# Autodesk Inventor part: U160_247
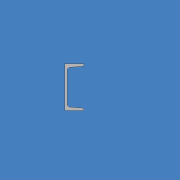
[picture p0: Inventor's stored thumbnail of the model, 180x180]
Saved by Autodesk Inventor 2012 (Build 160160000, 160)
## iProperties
Company: CAD-Verlag
Shininess: 64.0
Length Units: 11269
Angle Units: 11279
Time Units: 11290
Mass Units: 11283
Length Display Precision: 3
Angle Display Precision: 2
Compacted: True
Part Number: U160_247
Document SubType Name: Modeling
Created: 2004-09
Material: Standard
Designer: Greiling
Manufacturer: Standard
Standards Organization: Custom
Density: 1 g/cm^3
Density: 0.0
Volumn: 0.0
Area: 0.0
PropertySet Name: Model Information
Control State: 0
Master: False
Checked Out: False
Author: Jürgen Kronas
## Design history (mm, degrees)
sketch "Skizze1"
  geometry: L1 (0, 208)-(0, -16) reference; L2 (-6.607, 0)-(85.893, 0) reference; L3 (-6.607, 0)-(85.893, 0) reference; L4 (0, -16)-(0, 208) reference; L5 (0, 0)-(0, 160); L6 (65, 0)-(0, 0); L7 (65, 2.822)-(65, 0); L8 (17.163, 11.727)-(59.939, 8.305); L9 (7.5, 137.806)-(7.5, 22.194); L10 (65, 160)-(65, 157.178); L11 (59.939, 151.695)-(17.163, 148.273); L12 (0, 160)-(65, 160); A1 r 10.5 centre (18, 137.806) between (17.163, 148.273) and (7.5, 137.806); A2 r 10.5 centre (18, 22.194) between (7.5, 22.194) and (17.163, 11.727); A3 r 5.5 centre (59.5, 2.822) between (65, 2.822) and (59.939, 8.305); A4 r 5.5 centre (59.5, 157.178) between (59.939, 151.695) and (65, 157.178); 1 further point
  constraints: 16 end point, 8 point on circle, 4 centre point, 3 point on line
extrude "Extrusion1" new body sketch "Skizze1" distance "d0" = 247; taper "d1" = 0 deg
node "Volumenkörper1"
node "Volumenkörpern"
node "Oberflächenkörpern"
